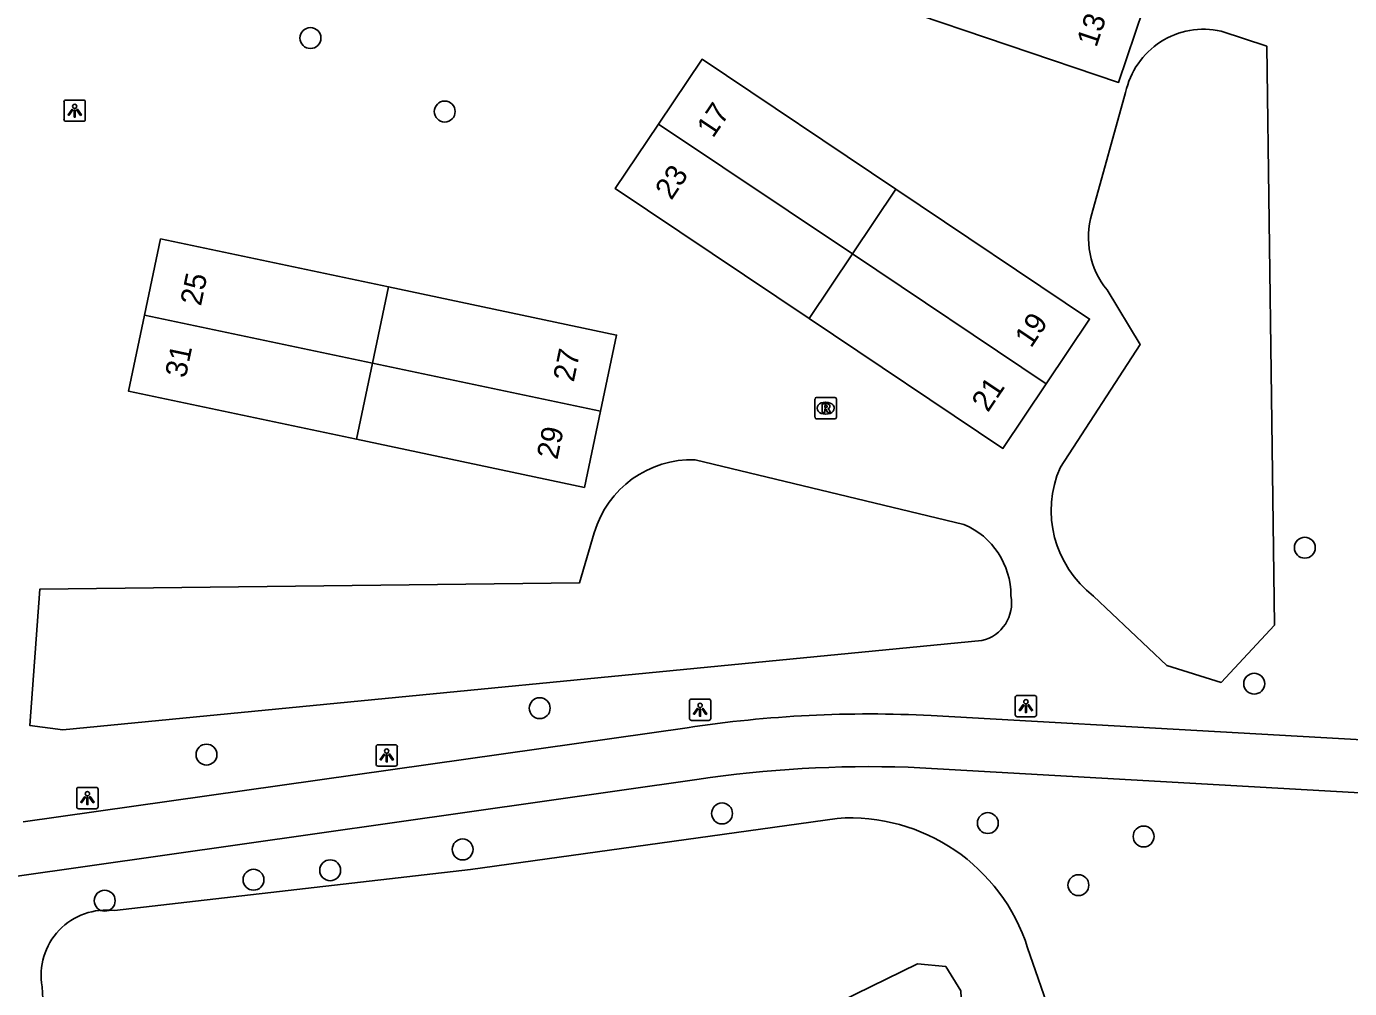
# Model space of a CAD drawing. Extents: x 159451 to 160663, y 388402 to 389723.
# Drawn here: x 159527.4 to 159589.3, y 389293.3 to 389338.3 of the extents above; entities that cross this region are included whole.
import ezdxf

# ---------------------------------------------------------------- set-up
doc = ezdxf.new("R2010")
doc.units = 0
for name, color, linetype in [('IMGEO_Boom', 7, 'Continuous'), ('IMGEO_Lichtpunt', 7, 'Continuous'), ('IMGEO_Meer_plas_ven_vijver', 7, 'Continuous'), ('IMGEO_Pand', 7, 'Continuous'), ('IMGEO_Pand_nummerreeks', 7, 'Continuous'), ('IMGEO_Rijbaan_lokaal_gesloten', 7, 'Continuous'), ('IMGEO_Rioolput', 7, 'Continuous')]:
    doc.layers.add(name, color=color, linetype=linetype)

msp = doc.modelspace()

# ---------------------------------------------------------------- linework, layer by layer
at = {"layer": 'IMGEO_Boom'}
for centre in [(159540.673, 389337.725), (159546.954, 389334.287), (159587.179, 389313.887), (159584.813, 389307.527), (159551.396, 389306.381), (159535.811, 389304.209), (159559.924, 389301.457), (159572.353, 389301.007), (159579.641, 389300.381), (159547.792, 389299.774), (159541.597, 389298.799), (159538.012, 389298.356), (159576.591, 389298.104), (159531.052, 389297.376)]:
    msp.add_circle(centre, 0.489, dxfattribs=at)
at = {"layer": 'IMGEO_Lichtpunt'}
for p, q in [((159529.148, 389334.732), (159529.148, 389333.925)), ((159529.148, 389334.732), (159529.148, 389333.925)), ((159530.05, 389334.827), (159529.242, 389334.827)), ((159530.05, 389334.827), (159529.242, 389334.827)), ((159530.144, 389333.925), (159530.144, 389334.732)), ((159530.144, 389333.925), (159530.144, 389334.732)), ((159529.242, 389333.831), (159530.05, 389333.831)), ((159529.242, 389333.831), (159530.05, 389333.831)), ((159558.401, 389306.713), (159558.401, 389305.906)), ((159558.401, 389306.713), (159558.401, 389305.906)), ((159559.303, 389306.808), (159558.495, 389306.808)), ((159559.303, 389306.808), (159558.495, 389306.808)), ((159559.397, 389305.906), (159559.397, 389306.713)), ((159559.397, 389305.906), (159559.397, 389306.713)), ((159573.635, 389306.883), (159573.635, 389306.076)), ((159573.635, 389306.883), (159573.635, 389306.076)), ((159574.537, 389306.978), (159573.729, 389306.978)), ((159574.537, 389306.978), (159573.729, 389306.978)), ((159574.631, 389306.076), (159574.631, 389306.883)), ((159574.631, 389306.076), (159574.631, 389306.883)), ((159558.495, 389305.812), (159559.303, 389305.812)), ((159558.495, 389305.812), (159559.303, 389305.812)), ((159573.729, 389305.982), (159574.537, 389305.982)), ((159573.729, 389305.982), (159574.537, 389305.982)), ((159543.741, 389304.576), (159543.741, 389303.769)), ((159543.741, 389304.576), (159543.741, 389303.769)), ((159544.643, 389304.671), (159543.835, 389304.671)), ((159544.643, 389304.671), (159543.835, 389304.671)), ((159544.737, 389303.769), (159544.737, 389304.576)), ((159544.737, 389303.769), (159544.737, 389304.576)), ((159543.835, 389303.675), (159544.643, 389303.675)), ((159543.835, 389303.675), (159544.643, 389303.675)), ((159529.744, 389302.581), (159529.744, 389301.774)), ((159529.744, 389302.581), (159529.744, 389301.774)), ((159530.646, 389302.676), (159529.838, 389302.676)), ((159530.646, 389302.676), (159529.838, 389302.676)), ((159530.74, 389301.774), (159530.74, 389302.581)), ((159530.74, 389301.774), (159530.74, 389302.581)), ((159529.838, 389301.68), (159530.646, 389301.68)), ((159529.838, 389301.68), (159530.646, 389301.68))]:
    msp.add_line(p, q, dxfattribs=at)
for points in [[(159529.522, 389334.396), (159529.561, 389334.368), (159529.373, 389334.106), (159529.335, 389334.133), (159529.522, 389334.396)], [(159529.624, 389334.348), (159529.671, 389334.348), (159529.671, 389334.026), (159529.624, 389334.026), (159529.624, 389334.348)], [(159529.734, 389334.368), (159529.772, 389334.395), (159529.959, 389334.133), (159529.92, 389334.105), (159529.734, 389334.368)], [(159558.775, 389306.377), (159558.814, 389306.349), (159558.626, 389306.087), (159558.588, 389306.114), (159558.775, 389306.377)], [(159558.877, 389306.329), (159558.924, 389306.329), (159558.924, 389306.007), (159558.877, 389306.007), (159558.877, 389306.329)], [(159558.987, 389306.349), (159559.025, 389306.376), (159559.212, 389306.114), (159559.173, 389306.086), (159558.987, 389306.349)], [(159574.009, 389306.547), (159574.048, 389306.519), (159573.86, 389306.257), (159573.822, 389306.284), (159574.009, 389306.547)], [(159574.111, 389306.499), (159574.158, 389306.499), (159574.158, 389306.177), (159574.111, 389306.177), (159574.111, 389306.499)], [(159574.221, 389306.519), (159574.259, 389306.546), (159574.446, 389306.284), (159574.407, 389306.256), (159574.221, 389306.519)], [(159544.115, 389304.24), (159544.154, 389304.212), (159543.966, 389303.95), (159543.928, 389303.977), (159544.115, 389304.24)], [(159544.217, 389304.192), (159544.264, 389304.192), (159544.264, 389303.87), (159544.217, 389303.87), (159544.217, 389304.192)], [(159544.327, 389304.212), (159544.365, 389304.239), (159544.552, 389303.977), (159544.513, 389303.949), (159544.327, 389304.212)], [(159530.118, 389302.245), (159530.157, 389302.217), (159529.969, 389301.955), (159529.931, 389301.982), (159530.118, 389302.245)], [(159530.22, 389302.197), (159530.267, 389302.197), (159530.267, 389301.875), (159530.22, 389301.875), (159530.22, 389302.197)], [(159530.33, 389302.217), (159530.368, 389302.244), (159530.555, 389301.982), (159530.516, 389301.954), (159530.33, 389302.217)]]:
    msp.add_lwpolyline(points, dxfattribs=at)
for centre in [(159529.647, 389334.53), (159574.134, 389306.681), (159558.9, 389306.511), (159544.24, 389304.374), (159530.243, 389302.379)]:
    msp.add_circle(centre, 0.0994, dxfattribs=at)
for centre, start, end in [((159529.242, 389334.732), 90, 180), ((159529.242, 389334.732), 90, 180), ((159530.05, 389334.732), 0, 90), ((159530.05, 389334.732), 0, 90), ((159529.242, 389333.925), 180, 270), ((159529.242, 389333.925), 180, 270), ((159530.05, 389333.925), 270, 0), ((159530.05, 389333.925), 270, 360), ((159558.495, 389306.713), 90, 180), ((159558.495, 389306.713), 90, 180), ((159559.303, 389306.713), 0, 90), ((159559.303, 389306.713), 0, 90), ((159573.729, 389306.883), 90, 180), ((159573.729, 389306.883), 90, 180), ((159574.537, 389306.883), 0, 90), ((159574.537, 389306.883), 0, 90), ((159573.729, 389306.076), 180, 270), ((159573.729, 389306.076), 180, 270), ((159574.537, 389306.076), 270, 0), ((159574.537, 389306.076), 270, 360), ((159558.495, 389305.906), 180, 270), ((159558.495, 389305.906), 180, 270), ((159559.303, 389305.906), 270, 0), ((159559.303, 389305.906), 270, 360), ((159543.835, 389304.576), 90, 180), ((159543.835, 389304.576), 90, 180), ((159544.643, 389304.576), 0, 90), ((159544.643, 389304.576), 0, 90), ((159543.835, 389303.769), 180, 270), ((159543.835, 389303.769), 180, 270), ((159544.643, 389303.769), 270, 0), ((159544.643, 389303.769), 270, 360), ((159529.838, 389302.581), 90, 180), ((159529.838, 389302.581), 90, 180), ((159530.646, 389302.581), 0, 90), ((159530.646, 389302.581), 0, 90), ((159529.838, 389301.774), 180, 270), ((159529.838, 389301.774), 180, 270), ((159530.646, 389301.774), 270, 0), ((159530.646, 389301.774), 270, 360)]:
    msp.add_arc(centre, 0.0946, start, end, dxfattribs=at)
at = {"layer": 'IMGEO_Meer_plas_ven_vijver'}
for points in [[(159583.265, 389338.049), (159585.405, 389337.346)], [(159585.405, 389337.346), (159585.616, 389320.948), (159585.756, 389310.259), (159583.269, 389307.588), (159580.724, 389308.383), (159577.303, 389311.626)], [(159577.217, 389329.496), (159578.8, 389335.179)], [(159575.746, 389317.652), (159579.475, 389323.392), (159577.93, 389325.941)], [(159558.673, 389317.997), (159571.236, 389314.976)], [(159572.076, 389309.541), (159529.1, 389305.373), (159527.548, 389305.578), (159528.023, 389311.95), (159553.255, 389312.241), (159553.948, 389314.586)], [(159531.514, 389296.911), (159548.156, 389298.841), (159565.312, 389301.228)], [(159574.217, 389295.171), (159576.492, 389288.625), (159580.643, 389278.999), (159585.177, 389266.997), (159588.35, 389258.709)], [(159571.755, 389279.564), (159571.085, 389293.162), (159570.386, 389294.298), (159569.066, 389294.418), (159562.535, 389291.222)], [(159528.272, 389290.814), (159528.13, 389293.352)]]:
    msp.add_lwpolyline(points, dxfattribs=at)
for centre, radius, start, end in [((159582.45, 389334.409), 3.73, 77.37547, 168.0885), ((159580.971, 389328.4), 3.911, 163.72297, 218.95888), ((159558.496, 389313.264), 4.736, 87.85852, 163.79288), ((159580.344, 389315.626), 5.024, 156.21696, 232.75756), ((159569.834, 389311.66), 3.6, 359.71074, 67.08044), ((159571.661, 389311.298), 1.806, 283.27906, 10.96701), ((159565.905, 389292.525), 8.723, 17.65678, 93.89774), ((159531.116, 389293.901), 3.036, 82.46825, 190.41944)]:
    msp.add_arc(centre, radius, start, end, dxfattribs=at)
at = {"layer": 'IMGEO_Pand'}
for points in [[(159579.637, 389339.107), (159578.47, 389335.651), (159568.144, 389339.143)], [(159556.956, 389333.705), (159558.987, 389336.732), (159568.05, 389330.657)], [(159563.994, 389324.607), (159554.929, 389330.685), (159556.956, 389333.705)], [(159566.021, 389327.63), (159556.956, 389333.705)], [(159568.05, 389330.657), (159566.021, 389327.63)], [(159568.05, 389330.657), (159577.112, 389324.582), (159575.085, 389321.557)], [(159532.912, 389324.767), (159533.664, 389328.332), (159544.327, 389326.082)], [(159566.021, 389327.63), (159563.994, 389324.607)], [(159566.021, 389327.63), (159575.085, 389321.557)], [(159544.327, 389326.082), (159543.575, 389322.518)], [(159544.327, 389326.082), (159554.99, 389323.833), (159554.238, 389320.27)], [(159542.824, 389318.958), (159532.162, 389321.21), (159532.912, 389324.767)], [(159543.575, 389322.518), (159532.912, 389324.767)], [(159575.085, 389321.557), (159573.057, 389318.531), (159563.994, 389324.607)], [(159542.824, 389318.958), (159543.575, 389322.518)], [(159543.575, 389322.518), (159554.238, 389320.27)], [(159554.238, 389320.27), (159553.487, 389316.706), (159542.824, 389318.958)]]:
    msp.add_lwpolyline(points, dxfattribs=at)
at = {"layer": 'IMGEO_Rijbaan_lokaal_gesloten'}
for points in [[(159568.631, 389303.617), (159612.27, 389301.143), (159611.84, 389301.566), (159612.513, 389301.851), (159611.86, 389302.198), (159612.655, 389302.565), (159612.044, 389302.952), (159612.757, 389303.197), (159612.166, 389303.421), (159612.776, 389303.614), (159569.711, 389306.038)], [(159558.3, 389305.469), (159527.236, 389301.062)], [(159526.743, 389298.498), (159558.75, 389303.048)]]:
    msp.add_lwpolyline(points, dxfattribs=at)
for centre, radius, start, end in [((159566.832, 389249.071), 57.04, 87.10675, 98.60253), ((159566.807, 389249.211), 54.436, 88.07992, 98.51159)]:
    msp.add_arc(centre, radius, start, end, dxfattribs=at)
at = {"layer": 'IMGEO_Rioolput'}
for p, q in [((159564.346, 389320.913), (159565.198, 389320.913)), ((159564.271, 389319.987), (159564.271, 389320.839)), ((159564.759, 389320.693), (159564.784, 389320.693)), ((159565.272, 389320.839), (159565.272, 389319.987)), ((159565.198, 389319.913), (159564.346, 389319.913)), ((159564.782, 389320.133), (159564.757, 389320.133))]:
    msp.add_line(p, q, dxfattribs=at)
for points in [[(159564.346, 389320.913), (159565.198, 389320.913)], [(159564.271, 389319.987), (159564.271, 389320.839)], [(159564.86, 389320.611), (159564.608, 389320.613), (159564.608, 389320.213)], [(159564.608, 389320.213), (159564.732, 389320.213), (159564.732, 389320.375), (159564.743, 389320.375)], [(159564.786, 389320.532), (159564.732, 389320.532), (159564.732, 389320.451)], [(159564.732, 389320.451), (159564.784, 389320.451)], [(159564.79, 389320.346), (159564.861, 389320.213), (159565.001, 389320.213), (159564.936, 389320.339)], [(159565.272, 389320.839), (159565.272, 389319.987)], [(159565.198, 389319.913), (159564.346, 389319.913)]]:
    msp.add_lwpolyline(points, dxfattribs=at)
for centre, radius, start, end in [((159564.348, 389320.837), 0.0765, 91.55205, 178.44795), ((159564.348, 389320.837), 0.0765, 91.55205, 178.44795), ((159565.196, 389320.837), 0.0765, 1.55205, 88.44795), ((159565.196, 389320.837), 0.0765, 1.55205, 88.44795), ((159564.742, 389320.322), 0.0533, 26.02933, 88.69889), ((159564.768, 389320.64), 0.19, 274.7715, 282.96867), ((159564.792, 389320.436), 0.0964, 77.00612, 93.18647), ((159564.806, 389320.493), 0.0378, 276.66336, 79.67722), ((159564.859, 389320.501), 0.109, 350.36119, 89.41601), ((159564.857, 389320.501), 0.112, 277.58423, 350.98172), ((159564.841, 389320.286), 0.108, 29.51342, 73.79051), ((159564.348, 389319.989), 0.0765, 181.55205, 268.44795), ((159564.348, 389319.989), 0.0765, 181.55205, 268.44795), ((159565.196, 389319.989), 0.0765, 271.55205, 358.44795), ((159565.196, 389319.989), 0.0765, 271.55205, 358.44795)]:
    msp.add_arc(centre, radius, start, end, dxfattribs=at)
for centre, major_axis, ratio, start_param, end_param in [((159564.758, 389320.413), (-0.387, 0.002), 0.722429, 4.712389, 7.853982), ((159564.783, 389320.413), (-0.39, 0.002), 0.717154, 1.570796, 4.712389)]:
    msp.add_ellipse(centre, major_axis=major_axis, ratio=ratio, start_param=start_param, end_param=end_param, dxfattribs=at)

# ---------------------------------------------------------------- texts
at = {"layer": 'IMGEO_Pand_nummerreeks'}
for s, rotation, p in [('13', 71.33325, (159577.429, 389337.254)), ('17', 56.13268, (159559.502, 389333.012)), ('23', 56.13268, (159557.552, 389330.107)), ('25', 78.08842, (159535.55, 389325.159)), ('19', 56.17278, (159574.375, 389323.193)), ('31', 78.08842, (159534.839, 389321.791)), ('27', 78.09415, (159552.987, 389321.604)), ('21', 56.17278, (159572.358, 389320.182)), ('29', 78.09415, (159552.221, 389317.972))]:
    msp.add_text(s, height=1, rotation=rotation, dxfattribs=at).set_placement(p)

doc.saveas('drawing.dxf')
